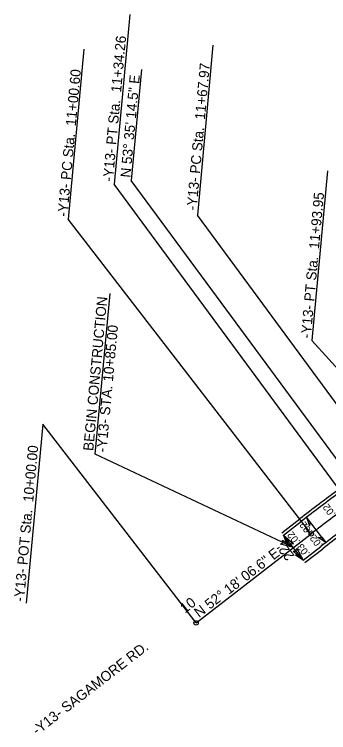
# Model space of a CAD drawing. Extents: x 2010838 to 2015151, y 441905 to 447792.
# Drawn here: x 2012312.4 to 2012529.9, y 446467.3 to 446963.8 of the extents above; entities that cross this region are included whole.
import ezdxf

# ---------------------------------------------------------------- set-up
doc = ezdxf.new("R2010")
doc.units = 0
for name, color, linetype in [('A-Wall-Blow', 7, 'Continuous'), ('A-Wall-Comp', 7, 'Continuous'), ('C-Building', 7, 'Continuous'), ('C-EOP 1', 7, 'Continuous'), ('C-Grave Plots', 7, 'Continuous'), ('CLRD', 7, 'Continuous'), ('Cont-2-Lidar', 7, 'Continuous'), ('Default_10ft_LIDAR_Contou', 7, 'Continuous'), ('Default_2FT_LIDAR_Contour', 7, 'Continuous'), ('s-Existing Major', 7, 'Continuous'), ('S-Existing Minor', 7, 'Continuous'), ('S-overhead electric', 7, 'Continuous'), ('TEXT-MED', 7, 'Continuous')]:
    doc.layers.add(name, color=color, linetype=linetype)

msp = doc.modelspace()

# ---------------------------------------------------------------- linework, layer by layer
at = {"layer": 'A-Wall-Blow'}
for p, q in [((2012527.99, 446598.7), (2012514.59, 446616.15)), ((2012512.19, 446586.49), (2012498.74, 446603.9))]:
    msp.add_line(p, q, dxfattribs=at)
at = {"layer": 'A-Wall-Comp'}
for points in [[(2012514.59, 446616.15), (2012516.66, 446610.17), (2012517.41, 446612.48)], [(2012498.74, 446603.9), (2012500.82, 446597.93), (2012501.56, 446600.24)], [(2012527.99, 446598.7), (2012522.75, 446602.24), (2012525.17, 446602.37)], [(2012512.19, 446586.49), (2012506.94, 446590.02), (2012509.36, 446590.15)]]:
    msp.add_lwpolyline(points, close=True, dxfattribs=at)
at = {"layer": 'C-Building'}
msp.add_line((2012517.33, 446604.37), (2012514.27, 446608.33), dxfattribs=at)
at = {"layer": 'C-EOP 1'}
msp.add_line((2012438.21, 446543.22), (2012433.31, 446549.55), dxfattribs=at)
at = {"layer": 'CLRD'}
msp.add_line((2012438.21, 446543.22), (2012517.81, 446604.74), dxfattribs=at)
msp.add_line((2012438.21, 446543.22), (2012517.81, 446604.74), dxfattribs=at)
msp.add_arc((2013435.06, 445417.87), 1500, 126.41263, 127.69817, dxfattribs=at)
msp.add_arc((2013435.06, 445417.87), 1500, 126.41263, 127.69817, dxfattribs=at)
at = {"layer": 'Default_10ft_LIDAR_Contou'}
for p, q in [((2012392.23, 446963.78), (2012381.43, 446846.33)), ((2012449.85, 446942.46), (2012439.06, 446825)), ((2012360.44, 446939.79), (2012349.64, 446822.33)), ((2012400.29, 446925.75), (2012393.24, 446849.01)), ((2012529.14, 446855.73), (2012518.34, 446738.27)), ((2012553.6, 446631.61), (2012393.24, 446849.01)), ((2012543.77, 446626.23), (2012381.43, 446846.33)), ((2012570.91, 446646.24), (2012439.06, 446825)), ((2012516.89, 446605.93), (2012349.64, 446822.33)), ((2012595.17, 446653.52), (2012518.34, 446738.27)), ((2012332.05, 446680.57), (2012320.67, 446556.79)), ((2012437.29, 446544.41), (2012332.05, 446680.57))]:
    msp.add_line(p, q, dxfattribs=at)
for centre in [(2012517.81, 446604.74), (2012438.21, 446543.22)]:
    msp.add_circle(centre, 1.5, dxfattribs=at)
at = {"layer": 's-Existing Major'}
for points in [[(2012497.98, 446600.43), (2012505.46, 446595.2), (2012496.59, 446597.61), (2012498.31, 446598.56)], [(2012503.01, 446595.83), (2012498.74, 446603.9), (2012505.54, 446597.72), (2012503.57, 446597.65)], [(2012507.91, 446594.56), (2012512.19, 446586.49), (2012505.39, 446592.68), (2012507.36, 446592.75)]]:
    msp.add_lwpolyline(points, close=True, dxfattribs=at)
at = {"layer": 'S-Existing Minor'}
for p, q in [((2012368.44, 446659.71), (2012378.67, 446770.95)), ((2012505.46, 446595.2), (2012368.44, 446659.71)), ((2012512.19, 446586.49), (2012498.74, 446603.9))]:
    msp.add_line(p, q, dxfattribs=at)
at = {"layer": 'S-overhead electric'}
for p, q in [((2012498.74, 446603.9), (2012511.08, 446613.44)), ((2012512.19, 446586.49), (2012524.53, 446596.03))]:
    msp.add_line(p, q, dxfattribs=at)
for radius in [1511, 1489]:
    msp.add_arc((2013435.06, 445417.87), radius, 126.41263, 127.69817, dxfattribs=at)
at = {"layer": 'TEXT-MED'}
for p, q in [((2012497.51, 446605.48), (2012509.86, 446615.02)), ((2012513.41, 446584.91), (2012525.76, 446594.45))]:
    msp.add_line(p, q, dxfattribs=at)
for radius in [1513, 1487]:
    msp.add_arc((2013435.06, 445417.87), radius, 126.41263, 127.69817, dxfattribs=at)

# ---------------------------------------------------------------- texts
at = {"layer": 'A-Wall-Blow'}
for s, rotation, p in [('.02', 126.7662, (2012534.98, 446618.56)), ('.02', 127.5302, (2012519.01, 446606.4)), ('.02', 127.6982, (2012510.45, 446599.55)), ('.02', 127.5302, (2012526.09, 446597.2)), ('.03', 127.6982, (2012517.2, 446591.19))]:
    msp.add_text(s, height=5, rotation=rotation, dxfattribs=at).set_placement(p)
at = {"layer": 'C-Grave Plots'}
for s, rotation, p in [('BEGIN CONSTRUCTION', 84.7467, (2012366.99, 446661.8)), ('-Y13- STA. 10+85.00', 84.7467, (2012376.13, 446660.96)), ("22'", 127.6982, (2012506.62, 446589.61)), ('-Y13- SAGAMORE RD.', 37.6982, (2012328.16, 446465.25))]:
    msp.add_text(s, height=7, rotation=rotation, dxfattribs=at).set_placement(p)
at = {"layer": 'Cont-2-Lidar'}
for s, rotation, p in [('N 53%%d 35\' 14.5" E', 84.7467, (2012392.75, 446850.75)), ('N 52%%d 18\' 06.6" E', 37.6982, (2012440.2, 446546.5))]:
    msp.add_text(s, height=7, rotation=rotation, dxfattribs=at).set_placement(p)
at = {"layer": 'Default_10ft_LIDAR_Contou'}
for s, p in [('-Y13- PT Sta.  11+34.26', (2012380.57, 446847.95)), ('-Y13- PC Sta.  11+67.97', (2012438.47, 446828.04)), ('-Y13- PC Sta.  11+00.60', (2012349.15, 446823.71)), ('-Y13- PT Sta.  11+93.95', (2012517.52, 446739.74)), ('-Y13- POT Sta.  10+00.00', (2012319.09, 446557.55))]:
    msp.add_text(s, height=7, rotation=84.7467, dxfattribs=at).set_placement(p)
at = {"layer": 'Default_2FT_LIDAR_Contour'}
msp.add_text('10', height=7, rotation=37.6982, dxfattribs=at).set_placement((2012430.48, 446549.51))

doc.saveas('drawing.dxf')
